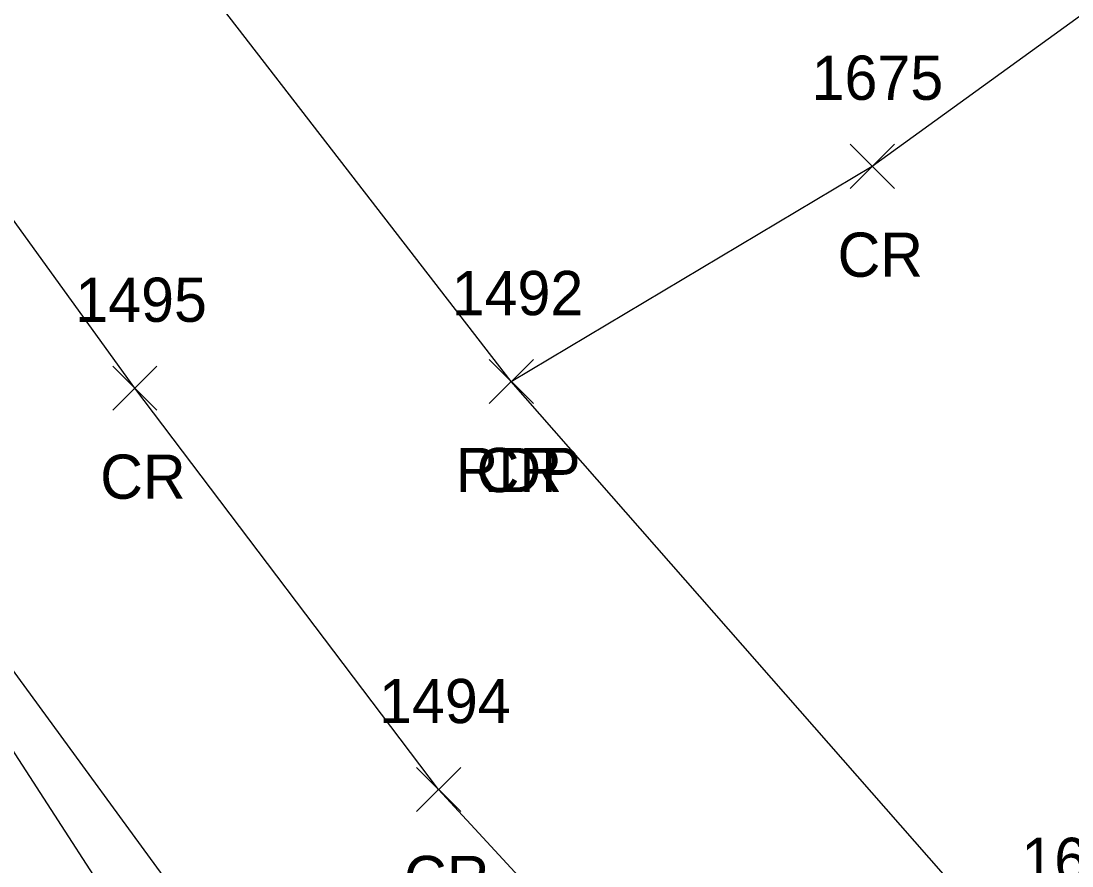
# Model space of a CAD drawing. Extents: x 1499292 to 1501024, y 534584 to 538043.
# Drawn here: x 1499887.83 to 1499935.33, y 537564.44 to 537602.65 of the extents above; entities that cross this region are included whole.
import ezdxf

# ---------------------------------------------------------------- set-up
doc = ezdxf.new("R2010")
doc.units = 0
for name, color, linetype in [('LELB', 7, 'Continuous'), ('P_A', 7, 'Continuous'), ('P_I', 7, 'Continuous'), ('P_TIC', 7, 'Continuous'), ('PET', 7, 'Continuous'), ('PRC', 7, 'Continuous')]:
    doc.layers.add(name, color=color, linetype=linetype)

msp = doc.modelspace()

# ---------------------------------------------------------------- linework, layer by layer
at = {"layer": 'LELB'}
msp.add_lwpolyline([(1499982.952, 537489.682), (1499966.995, 537494.973), (1499951.633, 537501.686), (1499942.165, 537508.923), (1499936.876, 537512.966), (1499930.432, 537522.297), (1499913.696, 537537.042), (1499897.541, 537554.09), (1499883.226, 537576.207), (1499873.982, 537589.177), (1499855.893, 537613.143), (1499849.418, 537619.303), (1499842.663, 537629.916), (1499836.966, 537639.791), (1499825.942, 537654.556), (1499819.306, 537659.466)], dxfattribs=at)
at = {"layer": 'P_TIC'}
for points in [[(1499925.303, 537595.084), (1499927.303, 537597.084)], [(1499927.303, 537595.084), (1499925.303, 537597.084)], [(1499908.986, 537585.349), (1499910.986, 537587.349)], [(1499910.986, 537585.349), (1499908.986, 537587.349)], [(1499908.986, 537585.349), (1499910.986, 537587.349)], [(1499910.986, 537585.349), (1499908.986, 537587.349)], [(1499891.971, 537585.047), (1499893.971, 537587.047)], [(1499893.971, 537585.047), (1499891.971, 537587.047)], [(1499905.704, 537566.903), (1499907.704, 537568.903)], [(1499907.704, 537566.903), (1499905.704, 537568.903)]]:
    msp.add_lwpolyline(points, dxfattribs=at)
at = {"layer": 'PET'}
for points in [[(1500289.781, 537338.292), (1500253.04, 537372.984), (1500224.755, 537395.044), (1500200.638, 537412.645), (1500169.786, 537433.283), (1500131.366, 537455.397), (1500082.939, 537477.86), (1500052.71, 537490.83), (1500028.687, 537501.079), (1500007.589, 537509.927), (1499989.795, 537518.651), (1499972.477, 537528.523), (1499952.084, 537542.885), (1499935.462, 537557.311), (1499909.986, 537586.349), (1499888.962, 537613.552)], [(1499898.168, 537558.628), (1499884.724, 537577.025)]]:
    msp.add_lwpolyline(points, dxfattribs=at)
at = {"layer": 'PRC'}
for points in [[(1499909.986, 537586.349), (1499926.303, 537596.084), (1499940.359, 537606.281), (1499956.988, 537614.658), (1499975.82, 537621.459), (1499996.949, 537627.676), (1500020.511, 537632.923), (1500051.029, 537643.891), (1500070.712, 537652.733), (1500093.189, 537667.353), (1500110.604, 537684.326), (1500128.972, 537704.003), (1500143.04, 537721.068)], [(1500278.962, 537330.133), (1500245.157, 537363.321), (1500217.073, 537386.354), (1500194.782, 537402.066), (1500161.587, 537424.072), (1500124.893, 537444.316), (1500077.396, 537466.829), (1500048.034, 537479.391), (1500024.096, 537489.275), (1500002.859, 537498.228), (1499984.27, 537507.122), (1499965.54, 537516.893), (1499943.097, 537532.261), (1499924.704, 537548.397), (1499906.704, 537567.903), (1499892.971, 537586.047), (1499884.57, 537597.666), (1499868.237, 537621.71), (1499849.203, 537650.099), (1499837.664, 537665.339), (1499832.024, 537672.415)]]:
    msp.add_lwpolyline(points, dxfattribs=at)

# ---------------------------------------------------------------- texts
at = {"layer": 'P_A'}
for s, p in [('CR', (1499924.736, 537591.084)), ('RDP', (1499907.474, 537581.349)), ('CR', (1499908.419, 537581.349)), ('CR', (1499891.404, 537581.047)), ('CR', (1499905.137, 537562.903))]:
    msp.add_text(s, height=2, dxfattribs=at).set_placement(p)
at = {"layer": 'P_I'}
for s, p in [('1675', (1499923.563, 537599.084)), ('1492', (1499907.293, 537589.349)), ('1492', (1499907.293, 537589.349)), ('1495', (1499890.278, 537589.047)), ('1494', (1499904.011, 537570.903)), ('1680', (1499933.044, 537563.722)), ('1680', (1499933.044, 537563.722))]:
    msp.add_text(s, height=2, dxfattribs=at).set_placement(p)

doc.saveas('drawing.dxf')
